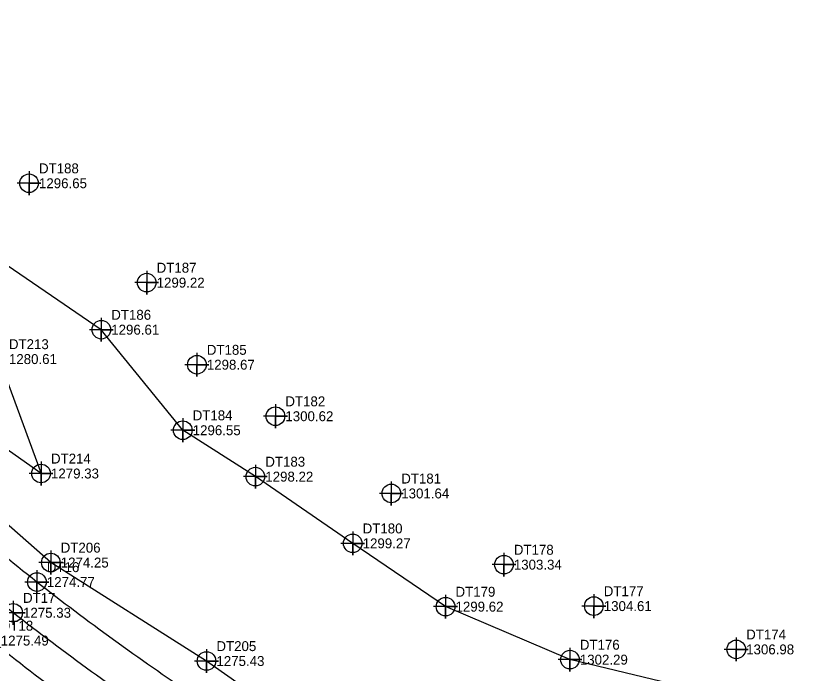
# Model space of a CAD drawing. Extents: x 1391270 to 1392151, y 960049 to 960667.
# Drawn here: x 1391741.8 to 1391945.1, y 960218.7 to 960384.3 of the extents above; entities that cross this region are included whole.
import ezdxf

# ---------------------------------------------------------------- set-up
doc = ezdxf.new("R2010")
doc.units = 0
for name, color, linetype in [('Exist DTM Breakline', 7, 'Continuous'), ('Exist DTM Breakline Cogo Elevation', 7, 'Continuous'), ('Exist DTM Breakline Cogo Number', 7, 'Continuous'), ('Exist DTM Breakline Cogo Point CELL', 7, 'Continuous'), ('Exist DTM Crownline', 7, 'Continuous'), ('Exist DTM Crownline Cogo Elevation', 7, 'Continuous'), ('Exist DTM Crownline Cogo Number', 7, 'Continuous'), ('Exist DTM Crownline Cogo Point CELL', 7, 'Continuous'), ('Exist DTM Regular Point CELL', 7, 'Continuous'), ('Exist DTM Regular Point Cogo Elevation', 7, 'Continuous'), ('Exist DTM Regular Point Cogo Number', 7, 'Continuous'), ('Exist Roads EOP', 7, 'Continuous'), ('Exist Roads EOP Cogo Elevation', 7, 'Continuous'), ('Exist Roads EOP Cogo Number', 7, 'Continuous'), ('Exist Roads EOP Cogo Point CELL', 7, 'Continuous')]:
    doc.layers.add(name, color=color, linetype=linetype)

msp = doc.modelspace()

# ---------------------------------------------------------------- linework, layer by layer
at = {"layer": 'Exist DTM Breakline'}
for points in [[(1391945.147, 960195.757), (1391918.09, 960213.421), (1391881.206, 960222.292), (1391849.896, 960235.631), (1391826.517, 960251.571), (1391802.004, 960268.368), (1391783.721, 960280.05), (1391763.211, 960305.363), (1391726.912, 960330.123), (1391710.789, 960346.476), (1391703.438, 960384.306)], [(1391698.511, 960324.915), (1391723.36, 960311.256), (1391737.445, 960297.964), (1391748.034, 960269.156), (1391727.16, 960283.875), (1391714.351, 960290.79), (1391702.491, 960302.562), (1391698.511, 960324.915)], [(1391918.848, 960154.955), (1391875.094, 960173.971), (1391832.683, 960194.523), (1391807.232, 960209.528), (1391789.699, 960221.943), (1391750.487, 960246.736), (1391714.022, 960278.792), (1391697.218, 960295.108)]]:
    msp.add_lwpolyline(points, dxfattribs=at)
at = {"layer": 'Exist DTM Breakline Cogo Point CELL'}
for points in [[(1391763.211, 960308.363), (1391763.211, 960302.363), (1391763.211, 960305.363), (1391766.211, 960305.363), (1391760.211, 960305.363)], [(1391783.721, 960283.05), (1391783.721, 960277.05), (1391783.721, 960280.05), (1391786.721, 960280.05), (1391780.721, 960280.05)], [(1391748.034, 960272.156), (1391748.034, 960266.156), (1391748.034, 960269.156), (1391751.034, 960269.156), (1391745.034, 960269.156)], [(1391802.004, 960271.368), (1391802.004, 960265.368), (1391802.004, 960268.368), (1391805.004, 960268.368), (1391799.004, 960268.368)], [(1391826.517, 960254.571), (1391826.517, 960248.571), (1391826.517, 960251.571), (1391829.517, 960251.571), (1391823.517, 960251.571)], [(1391750.487, 960249.736), (1391750.487, 960243.736), (1391750.487, 960246.736), (1391753.487, 960246.736), (1391747.487, 960246.736)], [(1391849.896, 960238.631), (1391849.896, 960232.631), (1391849.896, 960235.631), (1391852.896, 960235.631), (1391846.896, 960235.631)], [(1391881.206, 960225.292), (1391881.206, 960219.292), (1391881.206, 960222.292), (1391884.206, 960222.292), (1391878.206, 960222.292)], [(1391789.699, 960224.943), (1391789.699, 960218.943), (1391789.699, 960221.943), (1391792.699, 960221.943), (1391786.699, 960221.943)]]:
    msp.add_lwpolyline(points, dxfattribs=at)
for centre in [(1391763.211, 960305.363), (1391783.721, 960280.05), (1391748.034, 960269.156), (1391802.004, 960268.368), (1391826.517, 960251.571), (1391750.487, 960246.736), (1391849.896, 960235.631), (1391789.699, 960221.943), (1391881.206, 960222.292)]:
    msp.add_circle(centre, 2.344, dxfattribs=at)
at = {"layer": 'Exist DTM Crownline'}
msp.add_spline([(1391912.281, 960138.966), (1391866.83, 960157.169), (1391822.661, 960179.344), (1391780.998, 960205.13), (1391740.996, 960234.086), (1391702.853, 960265.768), (1391666.471, 960297.967)], degree=3, dxfattribs=at)
at = {"layer": 'Exist DTM Crownline Cogo Point CELL'}
msp.add_lwpolyline([(1391740.996, 960237.086), (1391740.996, 960231.086), (1391740.996, 960234.086), (1391743.996, 960234.086), (1391737.996, 960234.086)], dxfattribs=at)
msp.add_circle((1391740.996, 960234.086), 2.344, dxfattribs=at)
at = {"layer": 'Exist DTM Regular Point CELL'}
for points in [[(1391745.013, 960345.236), (1391745.013, 960339.236), (1391745.013, 960342.236), (1391748.013, 960342.236), (1391742.013, 960342.236)], [(1391774.648, 960320.216), (1391774.648, 960314.216), (1391774.648, 960317.216), (1391777.648, 960317.216), (1391771.648, 960317.216)], [(1391787.279, 960299.544), (1391787.279, 960293.544), (1391787.279, 960296.544), (1391790.279, 960296.544), (1391784.279, 960296.544)], [(1391807.056, 960286.578), (1391807.056, 960280.578), (1391807.056, 960283.578), (1391810.056, 960283.578), (1391804.056, 960283.578)], [(1391836.234, 960267.134), (1391836.234, 960261.134), (1391836.234, 960264.134), (1391839.234, 960264.134), (1391833.234, 960264.134)], [(1391864.586, 960249.204), (1391864.586, 960243.204), (1391864.586, 960246.204), (1391867.586, 960246.204), (1391861.586, 960246.204)], [(1391887.233, 960238.771), (1391887.233, 960232.771), (1391887.233, 960235.771), (1391890.233, 960235.771), (1391884.233, 960235.771)], [(1391923.089, 960227.867), (1391923.089, 960221.867), (1391923.089, 960224.867), (1391926.089, 960224.867), (1391920.089, 960224.867)]]:
    msp.add_lwpolyline(points, dxfattribs=at)
for centre in [(1391745.013, 960342.236), (1391774.648, 960317.216), (1391787.279, 960296.544), (1391807.056, 960283.578), (1391836.234, 960264.134), (1391864.586, 960246.204), (1391887.233, 960235.771), (1391923.089, 960224.867)]:
    msp.add_circle(centre, 2.344, dxfattribs=at)
at = {"layer": 'Exist Roads EOP'}
for points in [[(1391915.673, 960148.156), (1391871.111, 960166.209), (1391827.705, 960187.765), (1391786.031, 960213.485), (1391746.988, 960241.829), (1391709.378, 960273.178), (1391672.886, 960305.161)], [(1391909.259, 960130.384), (1391863.262, 960148.577), (1391817.991, 960171.223), (1391775.806, 960197.201), (1391735.389, 960227.09), (1391696.713, 960258.946), (1391660.088, 960291.389)]]:
    msp.add_spline(points, degree=3, dxfattribs=at)
at = {"layer": 'Exist Roads EOP Cogo Point CELL'}
msp.add_lwpolyline([(1391746.988, 960244.829), (1391746.988, 960238.829), (1391746.988, 960241.829), (1391749.988, 960241.829), (1391743.988, 960241.829)], dxfattribs=at)
msp.add_circle((1391746.988, 960241.829), 2.344, dxfattribs=at)

# ---------------------------------------------------------------- texts
at = {"layer": 'Exist DTM Breakline Cogo Elevation'}
for s, p in [('1296.61', (1391765.711, 960304.113)), ('1280.61', (1391739.945, 960296.714)), ('1296.55', (1391786.221, 960278.8)), ('1279.33', (1391750.534, 960267.906)), ('1298.22', (1391804.504, 960267.118)), ('1299.27', (1391829.017, 960250.321)), ('1274.25', (1391752.987, 960245.486)), ('1299.62', (1391852.396, 960234.381)), ('1275.43', (1391792.199, 960220.693)), ('1302.29', (1391883.706, 960221.042))]:
    msp.add_text(s, height=2.5, dxfattribs=at).set_placement(p)
at = {"layer": 'Exist DTM Breakline Cogo Number'}
for s, p in [('DT186', (1391765.711, 960307.863)), ('DT213', (1391739.945, 960300.464)), ('DT184', (1391786.221, 960282.55)), ('DT214', (1391750.534, 960271.656)), ('DT183', (1391804.504, 960270.868)), ('DT180', (1391829.017, 960254.071)), ('DT206', (1391752.987, 960249.236)), ('DT179', (1391852.396, 960238.131)), ('DT176', (1391883.706, 960224.792)), ('DT205', (1391792.199, 960224.443))]:
    msp.add_text(s, height=2.5, dxfattribs=at).set_placement(p)
at = {"layer": 'Exist DTM Crownline Cogo Elevation'}
msp.add_text('1275.33', height=2.5, dxfattribs=at).set_placement((1391743.496, 960232.836))
at = {"layer": 'Exist DTM Crownline Cogo Number'}
msp.add_text('DT17', height=2.5, dxfattribs=at).set_placement((1391743.496, 960236.586))
at = {"layer": 'Exist DTM Regular Point Cogo Elevation'}
for s, p in [('1296.65', (1391747.513, 960340.986)), ('1299.22', (1391777.148, 960315.966)), ('1298.67', (1391789.779, 960295.294)), ('1300.62', (1391809.556, 960282.328)), ('1301.64', (1391838.734, 960262.884)), ('1303.34', (1391867.086, 960244.954)), ('1304.61', (1391889.733, 960234.521)), ('1306.98', (1391925.589, 960223.617))]:
    msp.add_text(s, height=2.5, dxfattribs=at).set_placement(p)
at = {"layer": 'Exist DTM Regular Point Cogo Number'}
for s, p in [('DT188', (1391747.513, 960344.736)), ('DT187', (1391777.148, 960319.716)), ('DT185', (1391789.779, 960299.044)), ('DT182', (1391809.556, 960286.078)), ('DT181', (1391838.734, 960266.634)), ('DT178', (1391867.086, 960248.704)), ('DT177', (1391889.733, 960238.271)), ('DT174', (1391925.589, 960227.367))]:
    msp.add_text(s, height=2.5, dxfattribs=at).set_placement(p)
at = {"layer": 'Exist Roads EOP Cogo Elevation'}
for s, p in [('1274.77', (1391749.488, 960240.579)), ('1275.49', (1391737.889, 960225.84))]:
    msp.add_text(s, height=2.5, dxfattribs=at).set_placement(p)
at = {"layer": 'Exist Roads EOP Cogo Number'}
for s, p in [('DT16', (1391749.488, 960244.329)), ('DT18', (1391737.889, 960229.59))]:
    msp.add_text(s, height=2.5, dxfattribs=at).set_placement(p)

doc.saveas('drawing.dxf')
